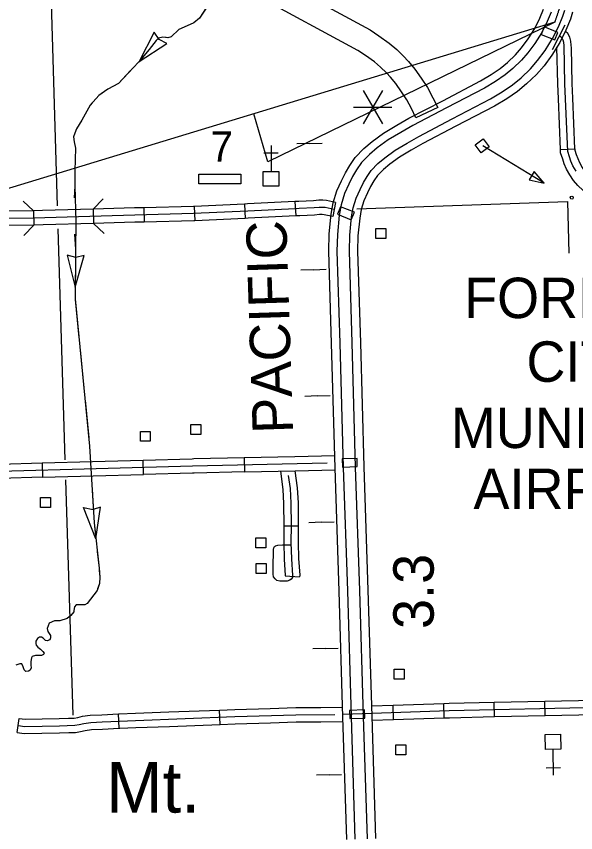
# Model space of a CAD drawing. Extents: x 155 to 3386, y 68 to 2138.
# Drawn here: x 1555.1 to 1722.1, y 551.2 to 794.9 of the extents above; entities that cross this region are included whole.
import ezdxf

# ---------------------------------------------------------------- set-up
doc = ezdxf.new("R2010")
doc.units = 0
for name, color, linetype in [('2', 7, 'Continuous'), ('Level 10', 7, 'Continuous'), ('Level 24', 7, 'Continuous'), ('Level 31', 7, 'Continuous'), ('Level 32', 7, 'Continuous'), ('Level 35', 7, 'Continuous'), ('Level 38', 7, 'Continuous'), ('Level 40', 7, 'Continuous'), ('Level 43', 7, 'Continuous'), ('Level 45', 7, 'Continuous'), ('Level 48', 7, 'Continuous'), ('Level 5', 7, 'Continuous'), ('Level 56', 7, 'Continuous'), ('Level 57', 7, 'Continuous')]:
    doc.layers.add(name, color=color, linetype=linetype)

msp = doc.modelspace()

# ---------------------------------------------------------------- linework, layer by layer
at = {"layer": '2'}
msp.add_line((1715.85, 793.15), (1068.19, 596), dxfattribs=at)
msp.add_lwpolyline([(1715.85, 793.15), (1630.26, 751.5), (1626.04, 765.81)], dxfattribs=at)
msp.add_open_spline([(1718.72, 829.66), (1719.86, 805.92), (1717.63, 798.36), (1715.85, 793.15)], degree=2, dxfattribs=at)
at = {"layer": 'Level 10'}
for p, q in [((1718.93, 792.28), (1715.13, 784.91)), ((1680.92, 767.67), (1674.44, 764.65))]:
    msp.add_line(p, q, dxfattribs=at)
for points in [[(1628.48, 808.35), (1630.28, 807.38), (1660.72, 790.9), (1663.38, 789.14), (1666.48, 786.94), (1668.69, 785.01), (1670.66, 783.12), (1672.24, 781.45), (1674.13, 779.15), (1676.03, 776.45), (1677.89, 773.68), (1679.47, 770.6), (1680.92, 767.67)], [(1674.44, 764.65), (1673.09, 767.39), (1671.73, 770.04), (1670.15, 772.4), (1668.44, 774.83), (1666.88, 776.73), (1665.6, 778.09), (1663.87, 779.73), (1662.05, 781.33), (1659.34, 783.25), (1657.04, 784.77), (1626.88, 801.1), (1625.08, 802.07)], [(1653.79, 549.25), (1652.65, 585.76), (1651.52, 623.35), (1650.29, 660.19), (1649.26, 697.24), (1648.4, 724.84), (1648.56, 729.97), (1649.13, 735.9), (1649.74, 739.26), (1650.85, 742.85), (1652.19, 745.86), (1653.37, 748.23), (1654.66, 750.44), (1656.31, 752.81), (1658.88, 755.52), (1661.38, 757.55), (1664.79, 760.06), (1668.7, 762.4), (1672.34, 764.49), (1682.42, 769.74), (1693.71, 775.65), (1696.91, 777.53), (1699.59, 779.39), (1701.78, 781.17), (1704.18, 783.47), (1705.98, 785.55), (1707.93, 788.17), (1709.88, 791.31), (1711.39, 794.34), (1712.48, 797.02)], [(1714.76, 796.19), (1713.61, 793.34), (1712.01, 790.13), (1709.94, 786.8), (1707.88, 784.03), (1705.94, 781.8), (1703.39, 779.34), (1701.05, 777.45), (1698.22, 775.48), (1694.89, 773.53), (1683.54, 767.59), (1673.5, 762.36), (1669.93, 760.3), (1666.14, 758.04), (1662.87, 755.63), (1660.53, 753.73), (1658.2, 751.27), (1656.71, 749.13), (1655.5, 747.07), (1654.38, 744.83), (1653.13, 742), (1652.11, 738.68), (1651.54, 735.57), (1650.99, 729.81), (1650.83, 724.84), (1651.69, 697.32), (1652.71, 660.27), (1653.95, 623.43), (1655.08, 585.84), (1656.21, 549.32)], [(1659.92, 549.44), (1658.79, 585.95), (1657.66, 623.55), (1656.43, 660.38), (1655.4, 697.43), (1654.55, 724.84), (1654.69, 729.58), (1655.22, 735.06), (1655.72, 737.8), (1656.61, 740.69), (1657.74, 743.24), (1658.77, 745.3), (1659.84, 747.13), (1661.09, 748.92), (1663.06, 751), (1665.14, 752.69), (1668.2, 754.94), (1671.81, 757.1), (1675.29, 759.1), (1685.26, 764.29), (1696.69, 770.28), (1700.22, 772.35), (1703.28, 774.48), (1705.85, 776.56), (1708.64, 779.24), (1710.77, 781.7), (1713.01, 784.71), (1715.25, 788.31), (1717, 791.81), (1718.26, 794.93), (1718.86, 796.8)], [(1721.2, 796.14), (1720.54, 794.1), (1719.22, 790.81), (1717.37, 787.13), (1715.02, 783.34), (1712.67, 780.18), (1710.4, 777.56), (1707.46, 774.73), (1704.74, 772.53), (1701.53, 770.3), (1697.87, 768.16), (1686.39, 762.14), (1676.46, 756.97), (1673.04, 755), (1669.54, 752.92), (1666.63, 750.77), (1664.71, 749.22), (1662.98, 747.39), (1661.89, 745.82), (1660.91, 744.14), (1659.94, 742.21), (1658.89, 739.84), (1658.08, 737.22), (1657.63, 734.72), (1657.12, 729.42), (1656.98, 724.84), (1657.83, 697.5), (1658.85, 660.45), (1660.09, 623.63), (1661.22, 586.02), (1662.35, 549.52)], [(1712.72, 791.8), (1711.8, 789.55), (1715.91, 787.88), (1716.83, 790.13)], [(1716.83, 790.13), (1712.72, 791.8)], [(1651.95, 738.11), (1651.03, 735.86), (1655.14, 734.19), (1656.06, 736.44)], [(1656.06, 736.44), (1651.95, 738.11)], [(1656.86, 662.93), (1652.42, 662.82)], [(1652.42, 662.82), (1652.48, 660.39), (1656.92, 660.5), (1656.86, 662.93)], [(1659.07, 587.86), (1654.64, 587.75)], [(1654.64, 587.75), (1654.7, 585.33), (1659.13, 585.44), (1659.07, 587.86)]]:
    msp.add_lwpolyline(points, dxfattribs=at)
at = {"layer": 'Level 31'}
for p, q in [((1717.59, 755.22), (1721.87, 755.4)), ((1721.87, 755.4), (1721.87, 755.4)), ((1650.46, 739.37), (1649.61, 735.17)), ((1623.15, 663.23), (1623.25, 658.94)), ((1562.82, 661.62), (1562.94, 657.34)), ((1562.82, 661.62), (1562.82, 661.62)), ((1593.1, 658.18), (1592.98, 662.47)), ((1593.1, 658.18), (1593.1, 658.18))]:
    msp.add_line(p, q, dxfattribs=at)
for points in [[(1720.83, 785.51), (1720.81, 786.35), (1720.7, 787.5), (1720.4, 788.67), (1719.74, 789.79), (1719.04, 790.45)], [(1722.22, 748.73), (1721.31, 750.3), (1720.72, 751.71), (1720.28, 752.95), (1719.76, 754.59), (1718.93, 774.82), (1718.67, 786.22), (1718.58, 787.14), (1718.4, 787.85), (1718.05, 788.44), (1717.43, 789.03), (1717.2, 789.15)], [(1716.97, 770.3), (1716.79, 774.75), (1716.53, 785.77)], [(1721.25, 770.47), (1721.07, 774.89), (1720.83, 785.51)], [(1717.59, 755.22), (1716.97, 770.3)], [(1721.87, 755.4), (1721.25, 770.47)], [(1726.69, 741.29), (1725.92, 741.76), (1724.36, 742.95), (1722.74, 744.44), (1721.47, 745.95), (1720.4, 747.61), (1719.39, 749.34), (1718.72, 750.94), (1718.24, 752.27), (1717.63, 754.21), (1717.59, 755.22)], [(1721.87, 755.4), (1721.89, 754.96), (1722.31, 753.64), (1722.72, 752.49), (1723.23, 751.25), (1724.05, 749.85), (1724.92, 748.5), (1725.84, 747.41), (1727.12, 746.24), (1728.33, 745.31), (1728.9, 744.97)], [(1650.46, 739.37), (1647.69, 739.94), (1646.63, 740.06), (1645.43, 740.06), (1643.87, 739.89), (1639.51, 739.7), (1638.3, 739.63)], [(1650.03, 737.27), (1647.35, 737.82), (1646.51, 737.91), (1645.54, 737.91), (1644.03, 737.75), (1639.61, 737.56), (1638.42, 737.49)], [(1649.61, 735.17), (1647.01, 735.7), (1646.39, 735.77), (1645.66, 735.77), (1644.19, 735.61), (1639.72, 735.42), (1638.53, 735.35)], [(1592.98, 662.47), (1607.65, 662.88), (1608.07, 662.89)], [(1608.07, 662.89), (1623.15, 663.23)], [(1623.15, 663.23), (1638.23, 663.57)], [(1638.23, 663.57), (1650.19, 663.84)], [(1419.85, 620.92), (1432.05, 626.35), (1465.97, 641.38), (1483.32, 649.51), (1497.11, 655.77), (1500.21, 656.93), (1502.6, 657.57), (1505.5, 657.9), (1509.88, 658.02), (1550.12, 659.12), (1607.71, 660.73), (1647.88, 661.64)], [(1547.74, 661.2), (1550.06, 661.26), (1562.82, 661.62)], [(1562.82, 661.62), (1577.9, 662.04)], [(1577.9, 662.04), (1592.98, 662.47)], [(1578.02, 657.76), (1593.1, 658.18)], [(1608.17, 658.6), (1607.76, 658.59), (1593.1, 658.18)], [(1623.25, 658.94), (1608.17, 658.6)], [(1623.25, 658.94), (1638.33, 659.28)], [(1638.33, 659.28), (1650.3, 659.55)], [(1562.94, 657.34), (1550.18, 656.98), (1547.86, 656.92)], [(1562.94, 657.34), (1578.02, 657.76)]]:
    msp.add_lwpolyline(points, dxfattribs=at)
at = {"layer": 'Level 32'}
for p, q in [((1623.25, 738.88), (1623.45, 734.6)), ((1638.31, 739.63), (1638.53, 735.35)), ((1578.06, 737.38), (1578.18, 733.09)), ((1593.15, 737.8), (1593.26, 733.52)), ((1608.18, 738.19), (1608.38, 733.91)), ((1635, 642.88), (1639.29, 642.85)), ((1635.41, 627.87), (1639.69, 627.63)), ((1682.86, 585.52), (1682.71, 589.8)), ((1697.91, 585.88), (1697.82, 590.16)), ((1712.99, 586.21), (1712.9, 590.5)), ((1667.78, 585), (1667.63, 589.28))]:
    msp.add_line(p, q, dxfattribs=at)
for points in [[(1623.25, 738.88), (1608.18, 738.19)], [(1638.31, 739.63), (1624.13, 738.92), (1623.25, 738.88)], [(1562.98, 736.94), (1560.23, 736.86)], [(1638.42, 737.49), (1624.23, 736.78), (1608.05, 736.04), (1590.47, 735.59), (1560.29, 734.72)], [(1578.06, 737.38), (1562.98, 736.94)], [(1593.15, 737.8), (1590.41, 737.73), (1578.06, 737.38)], [(1608.18, 738.19), (1607.97, 738.18), (1593.15, 737.8)], [(1593.26, 733.52), (1590.53, 733.45), (1578.18, 733.09)], [(1608.38, 733.91), (1608.12, 733.9), (1593.26, 733.52)], [(1623.45, 734.6), (1608.38, 733.91)], [(1638.53, 735.35), (1624.33, 734.64), (1623.45, 734.6)], [(1563.1, 732.66), (1560.36, 732.58)], [(1578.18, 733.09), (1563.1, 732.66)], [(1633.98, 659.18), (1634.69, 653.73), (1634.93, 649.54), (1635, 642.88), (1635, 642.84)], [(1638.29, 659.28), (1638.96, 654.13), (1639.22, 649.68), (1639.29, 642.89), (1639.29, 642.81)], [(1636.31, 657.87), (1636.83, 653.93), (1637.07, 649.61), (1637.14, 642.89), (1637.11, 637.86), (1637.25, 632.97), (1637.57, 628.05), (1637.53, 627.42), (1637.22, 626.88), (1636.76, 626.57), (1635.98, 626.35), (1635.09, 626.28), (1633.78, 626.32), (1632.9, 626.53), (1632.37, 626.99), (1631.95, 627.66), (1631.8, 628.41), (1631.84, 630.28), (1631.91, 635.73), (1631.98, 636.3), (1632.23, 636.69), (1632.55, 636.9), (1633.18, 637.11), (1634.56, 637.18), (1637.13, 637.18)], [(1635, 642.84), (1634.97, 637.84), (1635.11, 632.87), (1635.42, 628.04), (1635.41, 627.87)], [(1639.29, 642.81), (1639.25, 637.89), (1639.39, 633.07), (1639.72, 628.06), (1639.69, 627.63)], [(1667.63, 589.28), (1682.71, 589.8)], [(1682.71, 589.8), (1684.33, 589.86), (1697.82, 590.16)], [(1697.82, 590.16), (1712.9, 590.5)], [(1712.9, 590.5), (1727.98, 590.84)], [(1652.63, 586.62), (1684.39, 587.72), (1729.43, 588.73), (1739.79, 588.77), (1749.78, 588.45), (1783.18, 588.86), (1799.39, 589)], [(1661.13, 589.06), (1667.63, 589.28)], [(1661.26, 584.78), (1667.78, 585)], [(1667.78, 585), (1682.86, 585.52)], [(1682.86, 585.52), (1684.46, 585.57), (1697.91, 585.88)], [(1697.91, 585.88), (1712.99, 586.21)], [(1712.99, 586.21), (1728.08, 586.55)]]:
    msp.add_lwpolyline(points, dxfattribs=at)
at = {"layer": 'Level 35'}
msp.add_lwpolyline([(1576.27, 619.66), (1575.54, 619.24), (1574.96, 619.24), (1573.8, 619.24), (1572.96, 619.24), (1572.51, 618.7), (1572.33, 617.59), (1572.25, 617.19), (1571.4, 616.08), (1570.29, 615.14), (1568.15, 614.52), (1566.5, 614.43), (1564.95, 613.76), (1564.28, 612.2), (1564.55, 611.27), (1565.3, 610.06), (1565.3, 609.4), (1565.08, 608.82), (1564.37, 608.51), (1563.83, 608.59), (1563.12, 609.26), (1562.63, 609.62), (1562.01, 609.62), (1561.43, 609.17), (1560.94, 608.37), (1560.94, 607.75), (1561.07, 607.17), (1561.52, 606.64), (1562.36, 606.06), (1563.03, 605.3), (1563.39, 604.85), (1563.21, 604.41), (1562.63, 604.1), (1561.83, 604.1), (1560.81, 604.1), (1559.87, 603.79), (1559.65, 603.47), (1559.47, 602.32), (1559.47, 601.25), (1559.56, 600.45), (1559.29, 599.78), (1558.76, 599.42), (1558, 599.33), (1557.42, 599.82), (1557.16, 600.76), (1556.76, 601.65), (1556.18, 601.65), (1555.02, 601.25)], dxfattribs=at)
at = {"layer": 'Level 38'}
for points in [[(1557.12, 739.8), (1560.23, 736.86)], [(1578.06, 737.38), (1581, 740.49)], [(1560.36, 732.58), (1557.41, 729.46)], [(1581.3, 730.15), (1578.18, 733.09)]]:
    msp.add_lwpolyline(points, dxfattribs=at)
at = {"layer": 'Level 40'}
for p, q in [((1642.62, 756.99), (1638.85, 756.87)), ((1642.62, 756.99), (1646.39, 757.11)), ((1643.82, 719.29), (1640.05, 719.17)), ((1643.82, 719.29), (1647.59, 719.41)), ((1645.02, 681.6), (1641.25, 681.47)), ((1645.02, 681.6), (1648.79, 681.72)), ((1646.25, 643.9), (1642.48, 643.78)), ((1646.25, 643.9), (1650.02, 644.02)), ((1647.4, 606.21), (1643.63, 606.1)), ((1647.4, 606.21), (1651.17, 606.31)), ((1648.48, 568.51), (1644.71, 568.39)), ((1648.48, 568.51), (1652.25, 568.63))]:
    msp.add_line(p, q, dxfattribs=at)
at = {"layer": 'Level 43'}
for p, q in [((1596.31, 790.19), (1591.82, 781.47)), ((1597.72, 788), (1596.31, 790.19)), ((1600.07, 786.78), (1597.75, 787.97)), ((1591.82, 781.47), (1600.07, 786.78)), ((1572.84, 722.91), (1570.33, 723.63)), ((1570.33, 723.63), (1572.72, 714.12)), ((1572.72, 714.12), (1575.41, 723.55)), ((1575.41, 723.55), (1572.88, 722.91)), ((1575.19, 648.32), (1578.07, 647.72)), ((1578.85, 638.97), (1575.19, 648.32)), ((1580.29, 648.45), (1578.11, 647.73)), ((1578.85, 638.97), (1580.29, 648.45))]:
    msp.add_line(p, q, dxfattribs=at)
for points in [[(1614.27, 801.14), (1609.8, 794.42), (1608.07, 793), (1605.23, 791.68), (1603.6, 790.97), (1601.36, 788.83), (1600.35, 788.53), (1598.82, 788.73), (1597.6, 788.42), (1596.89, 787.71), (1594.76, 785.07), (1591.61, 781.2), (1585.61, 774.9), (1582.46, 773.17), (1579.71, 771.34), (1577.17, 768.39), (1574.63, 763.92), (1573.11, 761.37), (1572.19, 758.93), (1572.4, 757.51), (1572.8, 755.58), (1572.6, 748.76), (1572.6, 744.19), (1572.9, 733.71), (1572.8, 725.07), (1572.7, 710.62), (1576.97, 666.58), (1577.48, 658.38), (1578.32, 643.71), (1579.83, 630.17), (1580.1, 627.5), (1579.92, 625.63), (1579.21, 623.58), (1576.27, 619.66)], [(1611.6, 797.13), (1609.8, 794.42), (1608.07, 793), (1607.92, 792.93)], [(1607.92, 792.93), (1605.23, 791.68), (1603.6, 790.97), (1602.94, 790.34)], [(1599.82, 788.6), (1598.82, 788.73), (1597.6, 788.42), (1596.89, 787.71), (1594.76, 785.07), (1591.82, 781.47)], [(1589.24, 778.72), (1585.61, 774.9), (1582.46, 773.17), (1580.42, 771.81)], [(1577.81, 769.13), (1577.17, 768.39), (1574.63, 763.92), (1573.11, 761.37), (1572.32, 759.29)], [(1572.8, 755.6), (1572.8, 755.58), (1572.6, 748.76), (1572.6, 744.28), (1572.42, 740.77)], [(1572.48, 729.91), (1572.81, 725.43), (1572.8, 725.07), (1572.76, 719.78)], [(1572.76, 719.78), (1572.72, 714.12)], [(1572.73, 710.35), (1573.82, 699.09)], [(1574.18, 695.33), (1575.27, 684.07)], [(1575.64, 680.32), (1576.73, 669.06)], [(1577.79, 653.89), (1577.94, 650.24), (1578.32, 643.71), (1578.85, 638.97)], [(1579.27, 635.22), (1579.83, 630.17), (1579.89, 629.59)], [(1579.89, 629.59), (1580.1, 627.5), (1579.92, 625.63), (1579.37, 624.05)], [(1577.25, 620.96), (1576.27, 619.66)]]:
    msp.add_lwpolyline(points, dxfattribs=at)
at = {"layer": 'Level 45'}
for p, q in [((1560.26, 736.86), (1560.33, 732.58)), ((1615.94, 583.57), (1615.77, 587.85)), ((1555.35, 581.1), (1555.94, 585.35)), ((1585.82, 582.4), (1585.59, 586.68))]:
    msp.add_line(p, q, dxfattribs=at)
for points in [[(1560.26, 736.86), (1545.18, 736.63)], [(1560.29, 734.72), (1521.99, 734.14), (1494.87, 734.11), (1494, 733.95), (1493.39, 733.69), (1492.87, 733.27), (1492.49, 732.72), (1492.36, 732.27), (1492.29, 731.59), (1492.23, 730.17), (1492.81, 717.49)], [(1560.33, 732.58), (1545.24, 732.35)], [(1600.7, 587.27), (1615.77, 587.85)], [(1615.77, 587.85), (1620.31, 588.02), (1630.87, 588.34)], [(1630.87, 588.34), (1638.58, 588.58), (1646, 588.64)], [(1646, 588.64), (1652.57, 588.7)], [(1555.65, 583.22), (1557.62, 582.95), (1567.97, 583.18), (1572.6, 583.32), (1573.88, 583.55), (1575.26, 583.87), (1577.36, 584.14), (1580.75, 584.28), (1585.93, 584.55), (1590.74, 584.74), (1620.39, 585.88), (1638.62, 586.43), (1650.22, 586.53)], [(1555.94, 585.35), (1557.74, 585.1), (1567.92, 585.32), (1570.65, 585.4)], [(1570.65, 585.4), (1572.38, 585.45), (1573.45, 585.64), (1574.87, 585.98), (1577.18, 586.28), (1580.65, 586.42), (1585.59, 586.68)], [(1585.6, 586.68), (1585.83, 586.69), (1590.66, 586.88), (1600.7, 587.27)], [(1585.82, 582.4), (1586.03, 582.41), (1590.82, 582.6), (1600.87, 582.98)], [(1600.87, 582.98), (1615.94, 583.57)], [(1615.94, 583.57), (1620.46, 583.74), (1631, 584.06)], [(1631, 584.06), (1638.66, 584.29), (1646.04, 584.35)], [(1646.04, 584.35), (1652.7, 584.41)], [(1555.35, 581.1), (1557.49, 580.8), (1568.03, 581.04), (1570.77, 581.12)], [(1570.77, 581.12), (1572.82, 581.18), (1574.31, 581.45), (1575.64, 581.76), (1577.55, 582), (1580.85, 582.14), (1585.82, 582.4)]]:
    msp.add_lwpolyline(points, dxfattribs=at)
at = {"layer": 'Level 48'}
for p, q in [((1664.4, 772.75), (1658.69, 762.85)), ((1658.69, 772.75), (1664.4, 762.85)), ((1655.83, 767.8), (1667.26, 767.8))]:
    msp.add_line(p, q, dxfattribs=at)
at = {"layer": 'Level 5'}
for points in [[(1562.97, 886.74), (1567.34, 738.35)], [(1656.78, 737.47), (1719.66, 739.64)], [(1719.66, 739.64), (1720.06, 724.26)], [(1567.54, 731.52), (1569.64, 662.58)], [(1569.82, 656.59), (1571.96, 586.29)]]:
    msp.add_lwpolyline(points, dxfattribs=at)
at = {"layer": 'Level 56'}
for points in [[(1696.25, 755.96), (1693.87, 754.19), (1692.09, 756.58), (1694.47, 758.36)], [(1709.77, 748.6), (1708.25, 746.12), (1712.74, 745.08)], [(1609.64, 744.93), (1609.64, 747.79), (1622.14, 747.79), (1622.14, 744.93)], [(1662.5, 728.65), (1662.5, 731.63), (1665.48, 731.63), (1665.48, 728.65)], [(1607.26, 670.12), (1607.26, 673.09), (1610.25, 673.09), (1610.25, 670.12)], [(1592.15, 668.07), (1592.15, 671.04), (1595.13, 671.04), (1595.13, 668.07)], [(1562.37, 648.31), (1562.37, 651.28), (1565.35, 651.28), (1565.35, 648.31)], [(1626.67, 636.24), (1626.67, 639.22), (1629.66, 639.22), (1629.66, 636.24)], [(1626.76, 628.65), (1626.76, 631.62), (1629.74, 631.62), (1629.74, 628.65)], [(1667.93, 597.06), (1667.93, 600.04), (1670.91, 600.04), (1670.91, 597.06)], [(1668.42, 574.46), (1668.42, 577.44), (1671.4, 577.44), (1671.4, 574.46)]]:
    msp.add_lwpolyline(points, close=True, dxfattribs=at)
msp.add_lwpolyline([(1712.74, 745.08), (1694.43, 756.29)], dxfattribs=at)
msp.add_circle((1720.95, 740.8), 0.429, dxfattribs=at)
at = {"layer": 'Level 57'}
for p, q in [((1631.18, 756.34), (1631.18, 748.65)), ((1629.04, 754.2), (1633.32, 754.2)), ((1715.51, 568.41), (1715.38, 576.11)), ((1717.61, 570.59), (1713.33, 570.52))]:
    msp.add_line(p, q, dxfattribs=at)
for points in [[(1628.86, 744.19), (1628.86, 748.65), (1633.48, 748.65), (1633.48, 744.19)], [(1717.63, 580.6), (1717.7, 576.14), (1713.08, 576.07), (1713, 580.53)]]:
    msp.add_lwpolyline(points, close=True, dxfattribs=at)

# ---------------------------------------------------------------- texts
at = {"layer": 'Level 24'}
msp.add_text('Mt.', height=15.086, dxfattribs=at).set_placement((1581.97, 557.22))
at = {"layer": 'Level 40'}
msp.add_text('PACIFIC', height=12.069, rotation=91.8347, dxfattribs=at).set_placement((1637.76, 670.55))
at = {"layer": 'Level 48'}
msp.add_text('3.3', height=12.069, rotation=90, dxfattribs=at).set_placement((1679.74, 612.04))
at = {"layer": 'Level 56'}
msp.add_text('7', height=9.05, dxfattribs=at).set_placement((1613.1, 751.56))
at = {"layer": 'Level 57'}
for s, p in [('FORREST', (1688.8, 704.84)), ('CITY', (1707.42, 685.83)), ('MUNICIPAL', (1684.83, 666.06)), ('AIRPORT', (1691.6, 647.85))]:
    msp.add_text(s, height=12.069, dxfattribs=at).set_placement(p)

doc.saveas('drawing.dxf')
